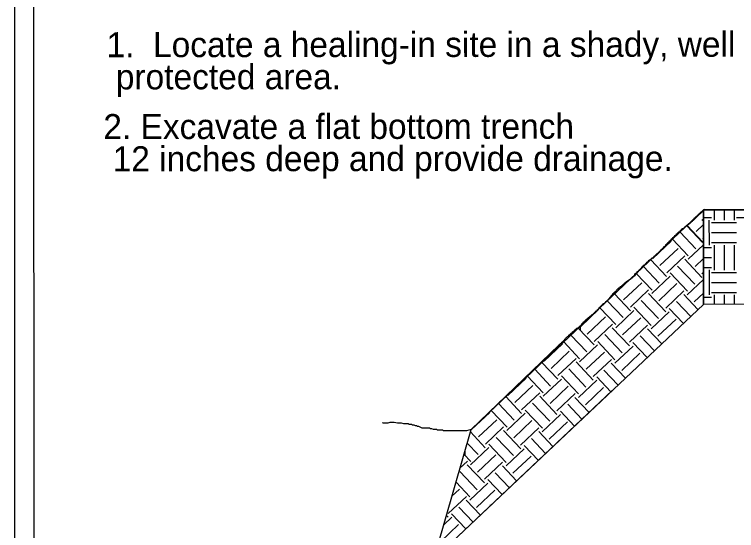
# Model space of a CAD drawing. Extents: x 1728110 to 1729925, y 1284214 to 1285339.
# Drawn here: x 1728252.2 to 1728451, y 1284944 to 1285086.1 of the extents above; entities that cross this region are included whole.
import ezdxf

# ---------------------------------------------------------------- set-up
doc = ezdxf.new("R2010")
doc.units = 0
doc.layers.add('Reforestation Detail CELL', color=7, linetype='Continuous')

msp = doc.modelspace()

# ---------------------------------------------------------------- linework, layer by layer
at = {"layer": 'Reforestation Detail CELL'}
for p, q in [((1728257.24, 1285281.67), (1728257.99, 1284287.57)), ((1728377.87, 1284971.87), (1728441.85, 1285032.25)), ((1728437.92, 1285028.37), (1728441.85, 1285032.09)), ((1728441.85, 1285032.25), (1728564.88, 1285032.34)), ((1728441.87, 1285006.28), (1728441.85, 1285032.25)), ((1728441.85, 1285032.25), (1728441.87, 1285006.28)), ((1728444.8, 1285032.25), (1728444.8, 1285029.43)), ((1728447.56, 1285032.25), (1728447.56, 1285029.43)), ((1728450.31, 1285032.26), (1728450.31, 1285029.43)), ((1728441.53, 1285029.39), (1728441.65, 1285029.64)), ((1728441.85, 1285030.16), (1728444.06, 1285030.17)), ((1728450.95, 1285030.17), (1728457.84, 1285030.18)), ((1728441.61, 1285023.33), (1728437.26, 1285027.92)), ((1728441.68, 1285023.39), (1728437.34, 1285027.99)), ((1728439.81, 1285026.37), (1728441.85, 1285028.3)), ((1728443.37, 1285029.48), (1728443.38, 1285022.59)), ((1728444.06, 1285028.79), (1728450.95, 1285028.79)), ((1728439.78, 1285021.6), (1728435.43, 1285026.19)), ((1728444.06, 1285026.03), (1728450.95, 1285026.04)), ((1728427.94, 1285018.94), (1728432.95, 1285023.68)), ((1728437.67, 1285019.61), (1728433.33, 1285024.21)), ((1728441.71, 1285024.37), (1728441.86, 1285024.51)), ((1728429.83, 1285016.94), (1728434.84, 1285021.67)), ((1728437.64, 1285018.71), (1728441.86, 1285022.69)), ((1728441.86, 1285021.95), (1728444.07, 1285021.95)), ((1728444.07, 1285023.28), (1728450.96, 1285023.28)), ((1728444.81, 1285022.59), (1728444.81, 1285015.7)), ((1728447.56, 1285022.59), (1728447.57, 1285015.7)), ((1728450.32, 1285022.59), (1728450.32, 1285015.7)), ((1728431.73, 1285014.94), (1728436.73, 1285019.67)), ((1728431.7, 1285013.96), (1728427.35, 1285018.56)), ((1728441.44, 1285013.69), (1728436.71, 1285018.7)), ((1728439.54, 1285016.7), (1728441.86, 1285018.9)), ((1728441.86, 1285019.19), (1728444.07, 1285019.19)), ((1728429.69, 1285012.07), (1728425.35, 1285016.67)), ((1728425.43, 1285016.75), (1728425.43, 1285016.75)), ((1728439.43, 1285011.79), (1728434.7, 1285016.8)), ((1728441.86, 1285016.43), (1728444.07, 1285016.43)), ((1728443.38, 1285015.74), (1728443.39, 1285008.86)), ((1728427.69, 1285010.18), (1728423.34, 1285014.78)), ((1728427.66, 1285009.27), (1728432.67, 1285014.01)), ((1728437.43, 1285009.9), (1728432.7, 1285014.91)), ((1728441.43, 1285014.7), (1728441.86, 1285015.11)), ((1728444.07, 1285015.06), (1728450.96, 1285015.06)), ((1728419.85, 1285007.51), (1728424.86, 1285012.24)), ((1728429.56, 1285007.27), (1728434.56, 1285012)), ((1728437.4, 1285008.93), (1728441.87, 1285013.14)), ((1728444.07, 1285012.3), (1728450.96, 1285012.31)), ((1728418.49, 1285010.2), (1728418.49, 1285010.2)), ((1728419.48, 1285011.13), (1728419.48, 1285011.13)), ((1728421.74, 1285005.51), (1728426.75, 1285010.24)), ((1728431.45, 1285005.27), (1728436.46, 1285010)), ((1728421.72, 1285004.53), (1728417.36, 1285009.14)), ((1728431.46, 1285004.26), (1728426.72, 1285009.27)), ((1728440.33, 1285004.82), (1728436.43, 1285008.95)), ((1728439.29, 1285006.93), (1728441.87, 1285009.36)), ((1728441.87, 1285008.21), (1728444.08, 1285008.22)), ((1728444.08, 1285009.55), (1728450.97, 1285009.55)), ((1728444.82, 1285008.86), (1728444.82, 1285006.28)), ((1728447.57, 1285008.86), (1728447.57, 1285006.28)), ((1728450.33, 1285008.86), (1728450.33, 1285006.28)), ((1728441.87, 1285006.28), (1728367.61, 1284936.13)), ((1728415.14, 1285007.05), (1728415.15, 1285007.04)), ((1728419.71, 1285002.64), (1728415.36, 1285007.25)), ((1728429.45, 1285002.36), (1728424.72, 1285007.37)), ((1728438.33, 1285002.93), (1728434.43, 1285007.06)), ((1728537.45, 1285006.35), (1728441.87, 1285006.28)), ((1728407.98, 1285000.08), (1728412.99, 1285004.82)), ((1728411.66, 1285003.75), (1728411.66, 1285003.75)), ((1728417.71, 1285000.75), (1728413.36, 1285005.36)), ((1728417.68, 1284999.84), (1728422.69, 1285004.58)), ((1728427.45, 1285000.47), (1728422.72, 1285005.48)), ((1728427.42, 1284999.5), (1728432.43, 1285004.23)), ((1728436.33, 1285001.04), (1728432.42, 1285005.17)), ((1728409.87, 1284998.08), (1728414.88, 1285002.81)), ((1728419.57, 1284997.84), (1728424.58, 1285002.57)), ((1728429.31, 1284997.5), (1728434.32, 1285002.23)), ((1728407.84, 1285000.15), (1728407.85, 1285000.15)), ((1728407.87, 1285000.18), (1728407.87, 1284999.14)), ((1728408.9, 1285001.15), (1728408.9, 1285001.15)), ((1728411.76, 1284996.08), (1728416.77, 1285000.81)), ((1728421.47, 1284994.83), (1728416.74, 1284999.84)), ((1728421.47, 1284995.84), (1728426.47, 1285000.57)), ((1728409.73, 1284993.21), (1728405.38, 1284997.82)), ((1728411.73, 1284995.1), (1728407.38, 1284999.72)), ((1728419.47, 1284992.94), (1728414.74, 1284997.94)), ((1728430.35, 1284995.39), (1728426.45, 1284999.53)), ((1728407.73, 1284991.32), (1728403.37, 1284995.93)), ((1728404.72, 1284997.21), (1728404.72, 1284997.2)), ((1728417.47, 1284991.04), (1728412.74, 1284996.05)), ((1728428.35, 1284993.5), (1728424.44, 1284997.63)), ((1728398, 1284990.65), (1728403, 1284995.39)), ((1728401.97, 1284994.61), (1728401.97, 1284994.6)), ((1728407.7, 1284990.41), (1728412.71, 1284995.15)), ((1728417.44, 1284990.07), (1728422.45, 1284994.8)), ((1728426.34, 1284991.61), (1728422.44, 1284995.74)), ((1728399.89, 1284988.65), (1728404.9, 1284993.38)), ((1728400.58, 1284993.3), (1728400.59, 1284993.3)), ((1728409.59, 1284988.41), (1728414.6, 1284993.14)), ((1728419.33, 1284988.06), (1728424.34, 1284992.8)), ((1728401.75, 1284985.67), (1728397.39, 1284990.29)), ((1728397.89, 1284990.76), (1728397.89, 1284990.75)), ((1728401.78, 1284986.65), (1728406.79, 1284991.38)), ((1728411.49, 1284985.4), (1728406.76, 1284990.41)), ((1728411.49, 1284986.41), (1728416.49, 1284991.14)), ((1728420.37, 1284985.97), (1728416.47, 1284990.1)), ((1728395.13, 1284988.16), (1728395.13, 1284988.15)), ((1728399.75, 1284983.78), (1728395.39, 1284988.4)), ((1728409.49, 1284983.51), (1728404.76, 1284988.51)), ((1728418.37, 1284984.07), (1728414.46, 1284988.2)), ((1728388.02, 1284981.23), (1728393.02, 1284985.96)), ((1728393.28, 1284986.41), (1728393.29, 1284986.41)), ((1728397.75, 1284981.89), (1728393.38, 1284986.51)), ((1728407.49, 1284981.61), (1728402.75, 1284986.62)), ((1728416.36, 1284982.18), (1728412.46, 1284986.31)), ((1728389.91, 1284979.22), (1728394.92, 1284983.95)), ((1728390.95, 1284984.21), (1728390.95, 1284984.2)), ((1728397.72, 1284980.99), (1728402.73, 1284985.72)), ((1728407.46, 1284980.64), (1728412.47, 1284985.37)), ((1728367.61, 1284936.13), (1728416.74, 1284982.53)), ((1728416.74, 1284982.53), (1728367.61, 1284936.13)), ((1728391.8, 1284977.22), (1728396.81, 1284981.95)), ((1728399.61, 1284978.98), (1728404.62, 1284983.71)), ((1728409.35, 1284978.64), (1728414.36, 1284983.37)), ((1728391.77, 1284976.24), (1728387.41, 1284980.87)), ((1728388.2, 1284981.61), (1728388.2, 1284981.6)), ((1728401.51, 1284975.97), (1728396.78, 1284980.98)), ((1728401.5, 1284976.98), (1728406.51, 1284981.71)), ((1728410.39, 1284976.54), (1728406.48, 1284980.67)), ((1728389.77, 1284974.35), (1728385.4, 1284978.97)), ((1728386.02, 1284979.56), (1728386.04, 1284979.56)), ((1728399.51, 1284974.08), (1728394.78, 1284979.08)), ((1728408.38, 1284974.64), (1728404.48, 1284978.77)), ((1728378.03, 1284971.8), (1728383.04, 1284976.53)), ((1728387.77, 1284972.46), (1728383.4, 1284977.08)), ((1728384.12, 1284977.76), (1728384.12, 1284977.75)), ((1728387.74, 1284971.56), (1728392.75, 1284976.29)), ((1728397.51, 1284972.18), (1728392.77, 1284977.19)), ((1728397.48, 1284971.21), (1728402.49, 1284975.94)), ((1728406.38, 1284972.75), (1728402.48, 1284976.88)), ((1728379.93, 1284969.79), (1728384.93, 1284974.52)), ((1728381.36, 1284975.16), (1728381.36, 1284975.15)), ((1728389.63, 1284969.55), (1728394.64, 1284974.28)), ((1728399.37, 1284969.21), (1728404.38, 1284973.94)), ((1728378.72, 1284972.67), (1728378.74, 1284972.67)), ((1728381.82, 1284967.79), (1728386.83, 1284972.52)), ((1728391.52, 1284967.55), (1728396.53, 1284972.28)), ((1728367.61, 1284936.13), (1728377.87, 1284971.87)), ((1728367.63, 1284936.13), (1728377.89, 1284971.87)), ((1728381.79, 1284966.82), (1728377.69, 1284971.16)), ((1728391.53, 1284966.54), (1728386.8, 1284971.55)), ((1728400.4, 1284967.11), (1728396.5, 1284971.24)), ((1728379.79, 1284964.92), (1728376.8, 1284968.08)), ((1728377.18, 1284969.47), (1728377.18, 1284969.4)), ((1728389.53, 1284964.65), (1728384.8, 1284969.65)), ((1728398.4, 1284965.21), (1728394.5, 1284969.34)), ((1728377.76, 1284962.13), (1728382.76, 1284966.86)), ((1728387.52, 1284962.75), (1728382.79, 1284967.76)), ((1728387.5, 1284961.78), (1728392.5, 1284966.51)), ((1728396.4, 1284963.32), (1728392.5, 1284967.45)), ((1728377.78, 1284963.03), (1728375.92, 1284965)), ((1728376.14, 1284965.82), (1728376.15, 1284965.82)), ((1728376.15, 1284965.87), (1728376.15, 1284964.82)), ((1728379.65, 1284960.12), (1728384.66, 1284964.85)), ((1728389.39, 1284959.78), (1728394.4, 1284964.51)), ((1728374.82, 1284961.18), (1728376.85, 1284963.09)), ((1728375.34, 1284963.07), (1728375.36, 1284963.07)), ((1728381.55, 1284957.11), (1728376.82, 1284962.12)), ((1728381.54, 1284958.12), (1728386.55, 1284962.85)), ((1728374.55, 1284960.31), (1728374.57, 1284960.31)), ((1728379.55, 1284955.21), (1728374.81, 1284960.22)), ((1728390.42, 1284957.68), (1728386.52, 1284961.81)), ((1728386.42, 1284953.89), (1728382.52, 1284958.02)), ((1728388.42, 1284955.79), (1728384.52, 1284959.91)), ((1728377.54, 1284953.32), (1728373.73, 1284957.36)), ((1728377.52, 1284952.35), (1728382.52, 1284957.08)), ((1728372.61, 1284953.47), (1728374.68, 1284955.42)), ((1728379.41, 1284950.35), (1728384.42, 1284955.08)), ((1728371.56, 1284948.69), (1728376.57, 1284953.42)), ((1728372.19, 1284952.09), (1728372.2, 1284952.09)), ((1728380.44, 1284948.25), (1728376.54, 1284952.38)), ((1728378.44, 1284946.36), (1728374.54, 1284950.48)), ((1728383.1, 1284951.09), (1728383.1, 1284950.74)), ((1728371.57, 1284947.68), (1728371.09, 1284948.18)), ((1728371.4, 1284949.33), (1728371.41, 1284949.33)), ((1728376.43, 1284944.46), (1728372.53, 1284948.59)), ((1728370.34, 1284945.57), (1728372.54, 1284947.65)), ((1728369.43, 1284940.92), (1728374.44, 1284945.65)), ((1728370.21, 1284945.2), (1728370.22, 1284945.2))]:
    msp.add_line(p, q, dxfattribs=at)
msp.add_lwpolyline([(1729918.82, 1285298.86), (1728252.17, 1285298.86), (1728252.17, 1284271.7), (1729918.82, 1284271.7)], close=True, dxfattribs=at)
for points in [[(1728441.85, 1285032.25), (1728442.15, 1285032.4), (1728441.93, 1285032.29), (1728441.7, 1285032.06), (1728441.59, 1285031.83), (1728441.36, 1285031.72), (1728441.13, 1285031.61), (1728440.91, 1285031.38), (1728440.68, 1285031.15), (1728440.46, 1285031.04), (1728440.34, 1285030.81), (1728440.11, 1285030.7), (1728440, 1285030.47), (1728439.78, 1285030.36), (1728439.55, 1285030.13), (1728439.32, 1285029.9), (1728439.21, 1285029.68), (1728438.98, 1285029.56), (1728438.87, 1285029.34), (1728438.64, 1285029.11), (1728438.42, 1285029), (1728438.3, 1285028.77), (1728438.08, 1285028.66), (1728437.96, 1285028.43), (1728437.74, 1285028.43), (1728437.51, 1285028.2), (1728437.28, 1285027.98), (1728437.06, 1285027.86), (1728436.83, 1285027.64), (1728436.6, 1285027.52), (1728436.49, 1285027.29), (1728436.27, 1285027.18), (1728436.04, 1285027.07), (1728435.81, 1285026.84), (1728435.58, 1285026.73), (1728435.47, 1285026.5), (1728435.25, 1285026.27), (1728435.02, 1285026.16), (1728434.79, 1285025.93), (1728434.57, 1285025.71), (1728434.34, 1285025.48), (1728434.11, 1285025.25), (1728433.89, 1285025.14), (1728433.77, 1285024.91), (1728433.55, 1285024.68), (1728433.32, 1285024.57), (1728433.21, 1285024.34), (1728432.98, 1285024.23), (1728432.87, 1285024), (1728432.64, 1285023.78), (1728432.42, 1285023.55), (1728432.19, 1285023.32), (1728431.96, 1285023.1), (1728431.74, 1285022.87), (1728431.51, 1285022.64), (1728431.28, 1285022.41), (1728431.17, 1285022.19), (1728430.94, 1285022.07), (1728430.72, 1285021.85), (1728430.6, 1285021.62), (1728430.38, 1285021.51), (1728430.26, 1285021.28), (1728430.04, 1285021.17), (1728429.92, 1285020.94), (1728429.7, 1285020.71), (1728429.47, 1285020.49), (1728429.24, 1285020.37), (1728429.13, 1285020.15), (1728428.91, 1285019.92), (1728428.68, 1285019.8), (1728428.45, 1285019.58), (1728428.23, 1285019.46), (1728428.11, 1285019.24), (1728427.89, 1285019.12), (1728427.66, 1285019.01), (1728427.43, 1285018.78), (1728427.21, 1285018.56), (1728426.98, 1285018.44), (1728426.75, 1285018.22), (1728426.53, 1285018.1), (1728426.41, 1285017.88), (1728426.19, 1285017.76), (1728426.07, 1285017.53), (1728425.85, 1285017.42), (1728425.73, 1285017.19), (1728425.51, 1285017.08), (1728425.28, 1285016.85), (1728425.05, 1285016.63), (1728424.83, 1285016.4), (1728424.72, 1285016.17), (1728424.49, 1285016.06), (1728424.38, 1285015.83), (1728424.15, 1285015.72), (1728423.92, 1285015.49), (1728423.81, 1285015.27), (1728423.58, 1285015.04), (1728423.47, 1285014.81), (1728423.24, 1285014.59), (1728423.02, 1285014.36), (1728422.9, 1285014.13), (1728422.68, 1285013.91)], [(1728452.96, 1285032.29), (1728452.62, 1285032.29), (1728452.4, 1285032.29), (1728441.85, 1285032.25), (1728441.85, 1285032.25), (1728452.28, 1285032.29)], [(1728422.68, 1285013.91), (1728422.34, 1285013.68), (1728422.11, 1285013.56), (1728422, 1285013.34), (1728421.77, 1285013.34), (1728421.66, 1285013.11), (1728421.43, 1285013), (1728421.21, 1285012.88), (1728420.98, 1285012.66), (1728420.75, 1285012.54), (1728420.53, 1285012.43), (1728420.3, 1285012.2), (1728420.07, 1285012.09), (1728419.96, 1285011.86), (1728419.73, 1285011.75), (1728419.62, 1285011.52), (1728419.39, 1285011.41), (1728419.17, 1285011.18), (1728418.94, 1285011.07), (1728418.71, 1285010.84), (1728418.49, 1285010.73), (1728418.26, 1285010.5), (1728418.03, 1285010.27), (1728417.92, 1285010.05), (1728417.69, 1285009.93), (1728417.58, 1285009.7), (1728417.35, 1285009.59), (1728417.13, 1285009.37), (1728416.9, 1285009.14), (1728416.68, 1285008.91), (1728416.56, 1285008.68), (1728416.34, 1285008.57), (1728416.22, 1285008.34), (1728416.11, 1285008.12), (1728415.88, 1285007.89), (1728415.66, 1285007.66), (1728415.54, 1285007.44), (1728415.32, 1285007.32), (1728415.09, 1285007.1), (1728414.86, 1285006.98), (1728414.75, 1285006.76), (1728414.52, 1285006.53), (1728414.3, 1285006.42), (1728414.07, 1285006.19), (1728413.84, 1285006.07), (1728413.73, 1285005.85), (1728413.5, 1285005.73), (1728413.39, 1285005.51), (1728413.17, 1285005.28), (1728412.94, 1285005.05), (1728412.82, 1285004.83), (1728412.6, 1285004.71), (1728412.49, 1285004.49), (1728412.26, 1285004.37), (1728412.03, 1285004.15), (1728411.81, 1285004.03), (1728411.69, 1285003.8), (1728411.47, 1285003.69), (1728411.35, 1285003.46), (1728411.13, 1285003.35), (1728410.9, 1285003.24), (1728410.79, 1285003.01), (1728410.56, 1285002.9), (1728410.33, 1285002.67), (1728410.11, 1285002.56), (1728409.88, 1285002.33), (1728409.65, 1285002.1), (1728409.43, 1285001.99), (1728409.31, 1285001.76), (1728409.09, 1285001.65), (1728408.98, 1285001.42), (1728408.75, 1285001.31), (1728408.52, 1285001.08), (1728408.3, 1285000.85), (1728408.18, 1285000.63), (1728408.07, 1285000.4), (1728407.84, 1285000.29), (1728407.62, 1285000.06), (1728407.39, 1284999.83), (1728407.16, 1284999.72), (1728406.94, 1284999.61), (1728406.71, 1284999.38), (1728406.48, 1284999.15), (1728406.26, 1284999.04), (1728406.14, 1284998.81), (1728405.92, 1284998.7), (1728405.69, 1284998.58), (1728405.58, 1284998.36), (1728405.35, 1284998.24), (1728405.13, 1284998.02), (1728404.9, 1284997.79), (1728404.67, 1284997.68), (1728404.56, 1284997.45), (1728404.33, 1284997.34), (1728404.22, 1284997.11), (1728403.99, 1284997), (1728403.88, 1284996.77), (1728403.65, 1284996.66), (1728403.54, 1284996.43), (1728403.31, 1284996.2), (1728403.09, 1284996.09)], [(1728423.23, 1285014.68), (1728422.98, 1285014.68), (1728422.98, 1285014.44)], [(1728422.98, 1285014.44), (1728422.98, 1285014.68), (1728423.23, 1285014.68)], [(1728423.29, 1285014.73), (1728423.29, 1285014.98), (1728423.56, 1285014.98)], [(1728423.6, 1285015.02), (1728423.6, 1285015.29), (1728423.88, 1285015.29)], [(1728409.53, 1285001.74), (1728409.53, 1285001.81), (1728409.84, 1285002.12), (1728410.04, 1285002.22)], [(1728409.25, 1285001.48), (1728409.23, 1285001.51), (1728409.28, 1285001.51)], [(1728403.09, 1284996.09), (1728402.97, 1284995.86), (1728402.75, 1284995.75), (1728402.63, 1284995.52), (1728402.41, 1284995.41), (1728402.29, 1284995.18), (1728402.07, 1284995.07), (1728377.87, 1284971.87), (1728377.87, 1284971.87), (1728401.96, 1284994.95)], [(1728397.77, 1284990.64), (1728397.92, 1284990.79), (1728397.93, 1284990.79)], [(1728385.92, 1284979.45), (1728385.69, 1284979.45), (1728385.92, 1284979.45)], [(1728377.87, 1284971.87), (1728376.6, 1284971.48), (1728376.22, 1284971.48), (1728375.65, 1284971.48), (1728375.08, 1284971.48), (1728374.7, 1284971.48), (1728374.32, 1284971.48), (1728373.94, 1284971.48), (1728373.56, 1284971.47), (1728373.18, 1284971.47), (1728372.8, 1284971.47), (1728372.42, 1284971.47), (1728372.04, 1284971.47), (1728371.47, 1284971.47), (1728371.09, 1284971.47), (1728370.71, 1284971.47), (1728370.33, 1284971.47), (1728370.14, 1284971.66), (1728369.76, 1284971.66), (1728369.38, 1284971.66), (1728369.01, 1284971.66), (1728368.63, 1284971.66), (1728368.44, 1284971.85), (1728368.06, 1284971.85), (1728367.49, 1284971.85), (1728367.11, 1284972.04), (1728366.73, 1284972.04), (1728366.54, 1284972.23), (1728366.16, 1284972.23), (1728365.78, 1284972.23), (1728365.4, 1284972.23), (1728365.02, 1284972.23), (1728364.45, 1284972.23), (1728364.07, 1284972.42), (1728363.5, 1284972.61), (1728363.12, 1284972.61), (1728362.93, 1284972.8), (1728362.55, 1284972.8), (1728362.17, 1284972.99), (1728361.79, 1284972.98), (1728361.61, 1284973.18), (1728361.23, 1284973.17), (1728360.85, 1284973.17), (1728360.66, 1284973.36), (1728360.28, 1284973.36), (1728359.9, 1284973.36), (1728359.33, 1284973.36), (1728358.76, 1284973.55), (1728357.62, 1284973.55), (1728356.67, 1284973.74), (1728356.29, 1284973.74), (1728355.91, 1284973.74), (1728355.53, 1284973.74), (1728354.96, 1284973.55), (1728354.39, 1284973.55), (1728354.02, 1284973.55), (1728353.64, 1284973.55), (1728353.45, 1284973.74), (1728353.45, 1284973.74)], [(1728378.52, 1284972.46), (1728377.87, 1284971.87)]]:
    msp.add_lwpolyline(points, dxfattribs=at)

# ---------------------------------------------------------------- texts
for s, p in [('1.  Locate a healing-in site in a shady, well', (1728277.53, 1285074.31)), (' protected area.', (1728277.53, 1285065.45)), ('2. Excavate a flat bottom trench ', (1728276.65, 1285051.76)), (' 12 inches deep and provide drainage.', (1728276.65, 1285042.9))]:
    msp.add_text(s, height=6.8898, rotation=0.0429, dxfattribs=at).set_placement(p)

doc.saveas('drawing.dxf')
